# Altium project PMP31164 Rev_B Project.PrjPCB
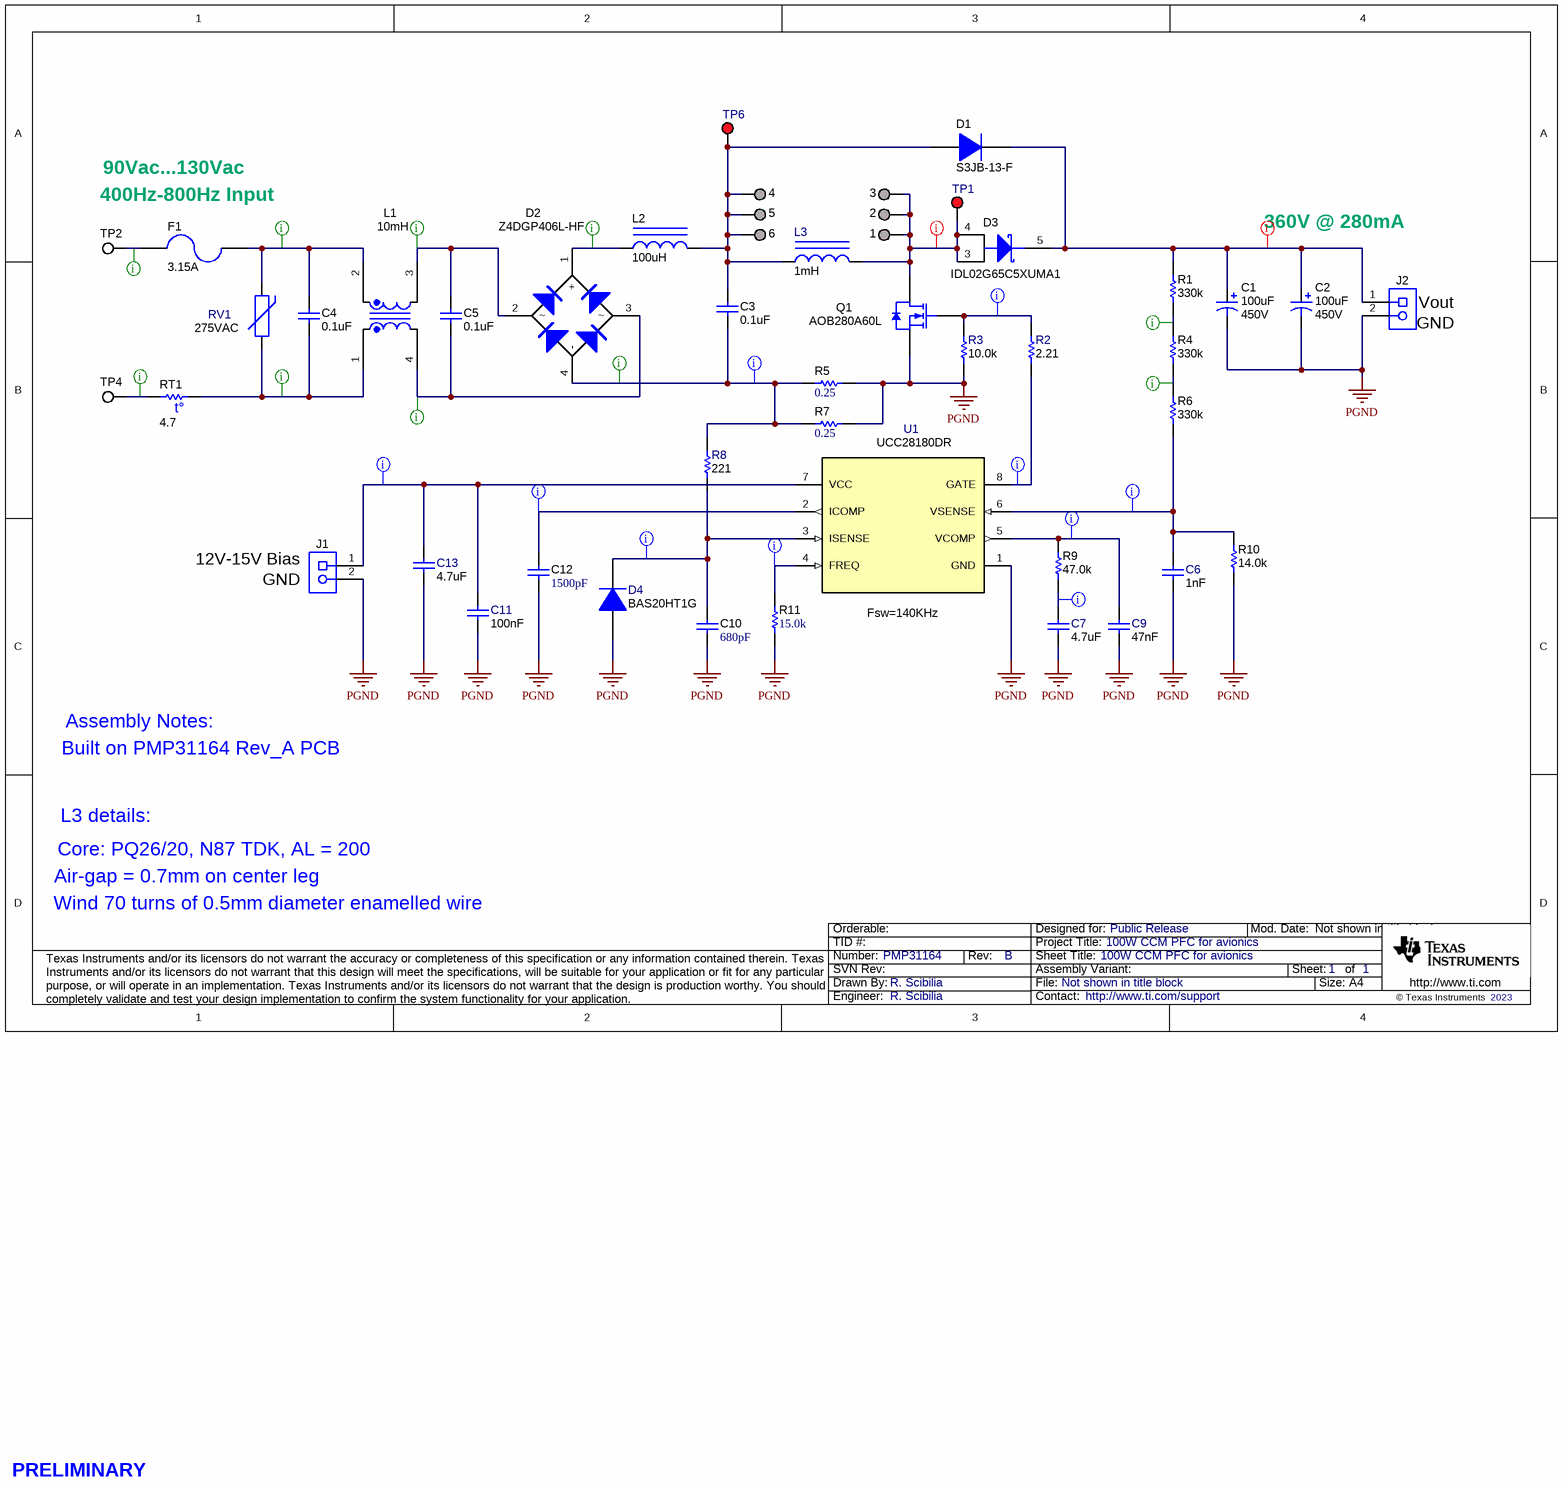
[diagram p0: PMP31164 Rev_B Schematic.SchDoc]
CopyrightYear: 2023; PCB_Layout: R. Scibilia; PCB_Rev: A; PRJ_Customer: Public Release; PRJ_Engineer: R. Scibilia; PRJ_Number: PMP31164; PRJ_Title: 100W CCM PFC for avionics; SCH_Rev: B; TechSupport: http://www.ti.com/support
1 sheet, 47 parts. Net scope: global (net labels, ports and power ports of the same name join across sheets).
Board file: PMP31164 Rev_A PCB.PcbDoc

## Sheet PMP31164 Rev_B Schematic.SchDoc: 100W CCM PFC for avionics
size A4; Date: Not shown in title block; ApprovedBy: Not shown in title block; CheckedBy: Not shown in title block; Author: Not shown in title block; CompanyName: Not shown in title block; DrawnBy: R. Scibilia; Engineer: Not shown in title block; Organization: Not shown in title block; Address1: Not shown in title block; Address2: Not shown in title block; Address3: Not shown in title block; Address4: Not shown in title block; DocumentNumber: 2; Revision: Use project parameter SCH_Rev; SheetNumber: 1; SheetTotal: 1; PageSetup: Record=PageOptions¦CenterHorizontal=True¦CenterVertical=True¦PrintScale=0.96¦XCorrection=1.00¦YCorrection=1.00¦PrintKind=0¦BorderSize=5000000¦LeftOffset=0¦BottomOffset=0¦Orientation=2¦PaperLength=4200¦PaperWidth=2970¦Scale=100¦PaperSource=7¦PrintQuality=600¦MediaType=1¦DitherType=10¦PaperKind=A3¦PrintScaleMode=1; PRJ_Engineer: R. Scibilia; PRJ_Number: PMP31164

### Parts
C1  VDC_V: 450V  ValueDisplayed: 100uF  [SMQ_2200X2500]  (hidden comment: ESMQ451VSN101MP25S)
C2  VDC_V: 450V  ValueDisplayed: 100uF  [SMQ_2200X2500]  (hidden comment: ESMQ451VSN101MP25S)
C3  ValueDisplayed: 0.1uF  [CAPRR1500W60L1750T550H1250]  (hidden comment: ECQ-U2A104ML)
C4  ValueDisplayed: 0.1uF  [CAPRR1500W60L1750T550H1250]  (hidden comment: ECQ-U2A104ML)
C5  ValueDisplayed: 0.1uF  [CAPRR1500W60L1750T550H1250]  (hidden comment: ECQ-U2A104ML)
C6  Cap_F: 1nF  [0603]  (hidden comment: C0603C102K5RACTU)
C7  ValueDisplayed: 4.7uF  [0805_HV]  (hidden comment: C2012X5R1E475K125AB)
C9  Cap_F: 47nF  [0603]  (hidden comment: 06033C473JAT2A)
C10  ValueDisplayed: 680pF  [0603]  (hidden comment: GRM1885C1H681JA01D)
C11  Cap_F: 100nF  [0603]  (hidden comment: C1608X7R1H104K080AA)
C12  ValueDisplayed: 1500pF  [0603]  (hidden comment: GRM1885C1H152JA01D)
C13  ValueDisplayed: 4.7uF  [0805_HV]  (hidden comment: C2012X5R1E475K125AB)
D1  S3JB-13-F  [SMB]
D2  Z4DGP406L-HF  [Z4-D]
D3  IDL02G65C5XUMA1  [PG-VSON-4]
D4  BAS20HT1G  [SOD-323]
F1  Irating_A: 3.15A  [FUSE_372]  (hidden comment: 37213150001)
J1  39357-0002  [MOLEX_39357-0002]  (value not drawn)
J2  39357-0002  [MOLEX_39357-0002]  (value not drawn)
L1  value 10mH  [WE-CMB_M]  (hidden comment: 744823210)
L2  ValueDisplayed: 100uH  [WE-PD_1210]  (hidden comment: 7447709101)
L3  value 1mH  [WE-PD_1210]  (hidden comment: TBD)
Q1  AOB280A60L  [DDPAK]
R1  ValueDisplayed: 330k  [1206]  (hidden comment: RC1206FR-07330KL)
R2  ValueDisplayed: 2.21  [0805_HV]  (hidden comment: CRCW08052R21FKEA)
R3  ValueDisplayed: 10.0k  [0603]  (hidden comment: CRCW060310K0FKEA)
R4  ValueDisplayed: 330k  [1206]  (hidden comment: RC1206FR-07330KL)
R5  ValueDisplayed: 0.25  [2010]  (hidden comment: CSRN2010FKR250)
R6  ValueDisplayed: 330k  [1206]  (hidden comment: RC1206FR-07330KL)
R7  ValueDisplayed: 0.25  [2010]  (hidden comment: CSRN2010FKR250)
R8  ValueDisplayed: 221  [0603]  (hidden comment: CRCW0603221RFKEA)
R9  ValueDisplayed: 47.0k  [0603]  (hidden comment: RC0603FR-0747KL)
R10  ValueDisplayed: 14.0k  [0603]  (hidden comment: CRCW060314K0FKEA)
R11  ValueDisplayed: 15.0k  [0603]  (hidden comment: RC0603FR-0715KL)
RT1  value 4.7  [S237]  (hidden comment: B57237S0479M000)
RV1  value 275VAC  [Epcos_B72220S0271K101]  (hidden comment: B72220S0271K101)
TP1  5000  [Keystone5000]  (value not drawn)
TP2  5012  [Keystone5012]  (value not drawn)
TP4  5012  [Keystone5012]  (value not drawn)
TP6  5000  [Keystone5000]  (value not drawn)
TP11  1  [TESTPOINT]  (no BOM)
TP12  2  [TESTPOINT]  (no BOM)
TP13  3  [TESTPOINT]  (no BOM)
TP14  4  [TESTPOINT]  (no BOM)
TP15  5  [TESTPOINT]  (no BOM)
TP16  6  [TESTPOINT]  (no BOM)
U1  UCC28180DR  [D0008A_N]

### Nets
PGND: C1.2(-) C2.2(-) C6.2 C7.2 C9.2 C10.2 C11.2 C12.2 C13.2 D4.2(A) J1.2 J2.2 Q1.3(S) R3.1 R5.2 R7.2 R10.1 R11.1 U1.1(GND)
NetC1_1: C1.1(+) C2.1(+) D1.1(K) D3.5(K) J2.1 R1.2
NetC3_1: C3.1 D1.2(A) L2.2 L3.1 TP6.1 TP14.1 TP15.1 TP16.1
NetC3_2: C3.2 D2.4(-) R5.1 R7.1 R8.2
NetC4_1: C4.1 F1.1 L1.2 RV1.2
NetC4_2: C4.2 L1.1 RT1.2 RV1.1
NetC5_1: C5.1 D2.2 L1.3
NetC5_2: C5.2 D2.3 L1.4
NetC6_1: C6.1 R6.1 R10.2 U1.6(VSENSE)
NetC7_1: C7.1 R9.1
NetC9_1: C9.1 R9.2 U1.5(VCOMP)
NetC10_1: C10.1 D4.1(K) R8.1 U1.3(ISENSE)
NetC11_1: C11.1 C13.1 J1.1 U1.7(VCC)
NetC12_1: C12.1 U1.2(ICOMP)
NetD2_1: D2.1(+) L2.1
NetD3_3: D3.3(A) D3.4(A) L3.2 Q1.2(D) TP1.1 TP11.1 TP12.1 TP13.1
NetF1_2: F1.2 TP2.1
NetQ1_1: Q1.1(G) R2.2 R3.2
NetR1_1: R1.1 R4.2
NetR2_1: R2.1 U1.8(GATE)
NetR4_1: R4.1 R6.2
NetR11_2: R11.2 U1.4(FREQ)
NetRT1_1: RT1.1 TP4.1

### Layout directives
rule Undefined; rule Clearance Constraint [Clearance = 30mil]: NetC1_1, NetC5_1, NetC5_2, NetD3_3
rule Undefined; rule Clearance Constraint [Clearance = 10mil]: NetC3_2, NetC6_1, NetC7_1, NetC9_1, NetC10_1, NetC11_1, NetC12_1, NetQ1_1, NetR2_1, NetR11_2
rule Undefined; rule Clearance Constraint [Clearance = 20mil]: NetC3_2, NetC4_1, NetC4_2, NetD2_1, NetF1_2, NetR1_1, NetR4_1, NetRT1_1

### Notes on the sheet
- 90Vac...130Vac
- 400Hz-800Hz Input
- 360V @ 280mA
- (near J2) Vout
- (near J2) GND
- (near J1) 12V-15V Bias
- (near J1) GND
- (near U1) Fsw=140KHz
- Assembly Notes:
- Built on PMP31164 Rev_A PCB
- L3 details:
- Core: PQ26/20, N87 TDK, AL = 200
- Air-gap = 0.7mm on center leg
- Wind 70 turns of 0.5mm diameter enamelled wire
- PRELIMINARY

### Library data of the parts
C1 C2 = CMP-0010054-2: CAP, AL, 100 uF, 450 V, +/- 20%, TH; Manufacturer: Chemi-Con; TaMin_C: -25°C; Polarized: Y; SizeAreaWB_mm2: 576; Value1: Unknown; U/M: EA; Value: 100uF; TaMax_C: 85°C; SizeZ_mm: 27; SizeX_mm: 22; Cap_Case: 22x25; SizeArea_mm2: 484; CompType: Capacitor; Cap_F: 100µF; IRMS_A: 930mA; AEC Category: Q200
C3-C5 = CMP-0012496-3: CAP, Film, 0.1 uF, 275 V, +/- 20%, TH; Manufacturer: Panasonic; TaMin_C: -40°C; Polarized: N; Value1: Unknown; Value: 0.1uF; TaMax_C: 100°C; Cap_Case: Radial 17.5x5.5x12.5; Value2: 275V; Cap_F: 100nF; AEC Category: Q200
C6 = CMP-0006847-4: CAP, CERM, 1000 pF, 50 V, +/- 10%, X7R, 0603; Manufacturer: Kemet; TaMin_C: -55°C; Polarized: N; SizeAreaWB_mm2: 4.68; Value1: Unknown; U/M: EA; Value: 1000pF; TaMax_C: 125°C; SizeZ_mm: 1; SizeX_mm: 1.6; SizeY_mm: 0.8; Value2: 50V; SizeArea_mm2: 1.28; AEC Category: Q200
C7 C13 = CMP-0007829-2: CAP, CERM, 4.7 uF, 25 V, +/- 10%, X5R, 0805; Manufacturer: TDK; TaMin_C: -55°C; Polarized: N; SizeAreaWB_mm2: 6.75; Value1: Unknown; U/M: EA; Value: 4.7uF; TaMax_C: 85°C; SizeZ_mm: 1.45; SizeX_mm: 2; SizeY_mm: 1.25; Cap_Case: 0805; Value2: 25V; SizeArea_mm2: 2.5; Cap_F: 4.7µF; AEC Category: Q200
C9 = CMP-0006757-5: CAP, CERM, 0.047 uF, 25 V, +/- 5%, X7R, 0603; Manufacturer: AVX; TaMin_C: -55°C; ESR_ohm: 52m; Polarized: N; SizeAreaWB_mm2: 4.68; Value1: 0.052 ohm; U/M: EA; TaMax_C: 125°C; SizeZ_mm: 1; SizeX_mm: 1.6; SizeY_mm: 0.8; Value2: 25V; SizeArea_mm2: 1.28; AEC Category: Q200
C10 = CMP-0007229-4: CAP, CERM, 680 pF, 50 V, +/- 5%, C0G/NP0, 0603; Manufacturer: MuRata; TaMin_C: -55°C; Polarized: N; SizeAreaWB_mm2: 4.68; Value1: Unknown; U/M: EA; Value: 680pF; TaMax_C: 125°C; SizeZ_mm: 1; SizeX_mm: 1.6; SizeY_mm: 0.8; Value2: 50V; SizeArea_mm2: 1.28; AEC Category: Q200
C11 = CMP-0007044-5: CAP, CERM, 0.1 uF, 50 V, +/- 10%, X7R, 0603; Manufacturer: TDK; TaMin_C: -55°C; ESR_ohm: 29.6m; Polarized: N; SizeAreaWB_mm2: 4.68; Value1: 0.0296 ohm; U/M: EA; Value: 0.1uF; TaMax_C: 125°C; SizeZ_mm: 1; SizeX_mm: 1.6; SizeY_mm: 0.8; Value2: 50V; SizeArea_mm2: 1.28; IRMS_A: 971.99mA; AEC Category: Q200
C12 = CMP-0007186-4: CAP, CERM, 1500 pF, 50 V, +/- 5%, C0G/NP0, 0603; Manufacturer: MuRata; TaMin_C: -55°C; Polarized: N; SizeAreaWB_mm2: 4.68; Value1: Unknown; U/M: EA; Value: 1500pF; TaMax_C: 125°C; SizeZ_mm: 1; SizeX_mm: 1.6; SizeY_mm: 0.8; Value2: 50V; SizeArea_mm2: 1.28; Cap_F: 1.5nF; AEC Category: Q200
D1 = CMP-0076890-2: Diode, Standard, 600 V, 3 A, SMB; Manufacturer: Diodes Inc.; Value1: 3A; TJmax_C: 150°C; RJC_CperW: 20.0; Green_REACh: Passed; Value2: 0.92V; Vf_V: 920mV; Green_Lifecycle: Active; SizeX_mm: 5.6; SizeAreaWB_mm2: 44.156; SizeZ_mm: 2.6; SizeArea_mm2: 21.336; Vr_V: 600V; SizeY_mm: 3.81; AEC Category: Q101
D2 = CMP-0029244-3: Diode, P-N-Bridge, 600 V, 4 A, Z4-D; Manufacturer: Comchip Technology; Value1: 4A; SizeZ_mm: 1.55; Value: 600V; SizeArea_mm2: 85.05; SizeY_mm: 8.1; SizeAreaWB_mm2: 126.25; Value2: 0.95V; Green_REACh: Incomplete; TJmax_C: 175°C; Green_Lifecycle: Not Set; Vf_V: 950mV; AEC Qualified: N; AEC Category: Q101; SizeX_mm: 10.5
D3 = CMP-0076996-2: Diode, Schottky, 650 V, 2 A, PG-VSON-4; Manufacturer: Infineon Technologies; Value2: 1.7V; Io_A: 2A; Value: 650V; Green_Lifecycle: Not Set; SizeZ_mm: 1.1; SizeAreaWB_mm2: 100.0; TJmax_C: 150°C; AEC Category: Q101; SizeArea_mm2: 64.0; SizeX_mm: 8.0; Green_REACh: Incomplete
D4 = CMP-0029150-2: Diode, Switching, 200 V, 0.2 A, AEC-Q101, SOD-323; Manufacturer: ON Semiconductor; Value2: 1.25V; Value1: 0.2A; SizeZ_mm: 1; Green_REACh: Incomplete; SizeArea_mm2: 3.645; Vr_V: 200V; SizeX_mm: 2.7; TJmax_C: 150°C; Io_A: 200mA; Value: 200V; Green_Lifecycle: Not Set; SizeAreaWB_mm2: 8.695; AEC Qualified: Y; AEC Category: Q101; SizeY_mm: 1.35
F1 = CMP-0003557-2: Fuse, 3.15 A, 250VAC/VDC, TH; Manufacturer: Littelfuse; VAC_V: 250V
J1 J2 = CMP-0055341-1: Terminal Block, 3.5 mm, 2x1, Tin, TH; Manufacturer: Molex; CNHeader: FALSE; Green_Lifecycle: Not Set; Green_REACh: Incomplete; CT: TRUE
L1 = CMP-0076828-1: Coupled inductor, 10 mH, 2 A, 0.125 ohm, TH; Manufacturer: Wurth Elektronik; SizeAreaWB_mm2: 513.0; SizeArea_mm2: 425.0; AEC Category: Q200; SizeZ_mm: 26.5; SizeY_mm: 17.0; DCR_ohm: 0.125; SizeX_mm: 25.0
L2 = CMP-0064536-2: Inductor, Shielded Drum Core, Ferrite, 100 uH, 2.5 A, 0.1 ohm, SMD; Manufacturer: Wurth Elektronik; Isat: 3.1A @ 10% inductance drop; Irms: 2.5A @ 40C rise; Green_Lifecycle: Active; SizeAreaWB_mm2: 196; DCR_ohm: 0.1; Green_REACh: Passed; Value1: 0.1 ohm; Value: 100uH; Imax_A: 2.5A; SizeZ_mm: 10; SizeX_mm: 12; SizeArea_mm2: 144; Ind_H: 100µH; AEC Category: Q200
L3 = CMP-0064759-2: Inductor, Ferrite, 1mH, 0.3 Ohm, te, 330 uH, 4 A(sat), TH; Isat: 4A @ 10% inductance drop; Irms: 2A @ 40C rise; Green_Lifecycle: Active; SizeAreaWB_mm2: 196; DCR_ohm: 0.3; Green_REACh: Passed; Value1: 0.3 ohm; Imax_A: 4A; SizeZ_mm: 10; SizeX_mm: 12; Value2: 2A; SizeArea_mm2: 144; AEC Category: Q200
Q1 = CMP-0081192-2: MOSFET, N-CH, 650 V, 56 A, DDPAK; Alternate Manufacturer: None; Manufacturer: Alpha & Omega; AEC Qualified: N; IdsMax_A: 56A; SizeArea_mm2: 154.8892; Value2: 23.5 nC; ChMode: Enhancement; QgTyp_nC: 20; VdsMax_V: 650V; SizeX_mm: 15.245; SizeZ_mm: 4.445; Vgs_V: 20V; SizeAreaWB_mm2: 209.6992; Value1: 0.28 ohm; AEC Category: Q101; SizeY_mm: 10.16
R1 R4 R6 = CMP-0018205-2: RES, 330 k, 1%, 0.25 W, 1206; Manufacturer: Yageo America; Power_W: 250mW; TempCo: 100 ppm/C; U/M: EA; Value: 330k; SizeX_mm: 3.2; SizeY_mm: 1.6; SizeZ_mm: 1.35; Value2: 0.25W; SizeArea_mm2: 5.12; VDC_V: 200V; AEC Category: Q200
R2 = CMP-0021145-3: RES, 2.21, 1%, 0.125 W, AEC-Q200 Grade 0, 0805; Manufacturer: Vishay-Dale; Power_W: 125mW; TempCo: 100 ppm/C; Value_Code: 2R21; Value: 2.21; EIA_Code: E96; SizeX_mm: 2; SizeY_mm: 1.25; SizeZ_mm: 1.45; Value2: 0.125W; SizeArea_mm2: 2.5; AEC Qualified: Y; VDC_V: 150V; AEC Category: Q200; AEC Grade: 0
R3 = CMP-0021998-4: RES, 10.0 k, 1%, 0.1 W, AEC-Q200 Grade 0, 0603; Manufacturer: Vishay-Dale; Power_W: 100mW; TempCo: 100 ppm/C; Value_Code: 10k0; Value: 10.0k; EIA_Code: E96; Res_ohm: 10k; SizeX_mm: 1.6; SizeY_mm: 0.8; SizeZ_mm: 1; Value2: 0.1W; SizeArea_mm2: 1.28; AEC Qualified: Y; VDC_V: 75V; AEC Category: Q200; AEC Grade: 0
R5 R7 = CMP-0016526-2: RES, 0.25, 1%, 1 W, 2010; Manufacturer: Stackpole Electronics Inc; Power_W: 1W; TempCo: 250 ppm/C; Value_Code: R250; U/M: EA; Value: 0.25; SizeX_mm: 5; SizeY_mm: 2.5; SizeZ_mm: 1.66; SizeArea_mm2: 12.5; AEC Category: Q200
R8 = CMP-0022217-5: RES, 221, 1%, 0.1 W, AEC-Q200 Grade 0, 0603; Manufacturer: Vishay-Dale; Power_W: 100mW; TempCo: 100 ppm/C; Value_Code: 221R; Value: 221; EIA_Code: E96; SizeX_mm: 1.6; SizeY_mm: 0.8; SizeZ_mm: 1; Value2: 0.1W; SizeArea_mm2: 1.28; AEC Qualified: Y; VDC_V: 75V; AEC Category: Q200; AEC Grade: 0
R9 = CMP-0023133-5: RES, 47.0 k, 1%, 0.1 W, 0603; Manufacturer: Yageo; Power_W: 100mW; TempCo: 100 ppm/C; Value_Code: 47k0; Value: 47.0k; Res_ohm: 47k; SizeX_mm: 1.6; SizeY_mm: 0.8; SizeZ_mm: 1; Value2: 0.1W; SizeArea_mm2: 1.28; AEC Qualified: N; VDC_V: 75V; AEC Category: Q200; SizeAreaWB_mm2: 4.68
R10 = CMP-0022054-4: RES, 14.0 k, 1%, 0.1 W, AEC-Q200 Grade 0, 0603; Manufacturer: Vishay-Dale; Power_W: 100mW; TempCo: 100 ppm/C; Value_Code: 14k0; Value: 14.0k; EIA_Code: E96; Res_ohm: 14k; SizeX_mm: 1.6; SizeY_mm: 0.8; SizeZ_mm: 1; Value2: 0.1W; SizeArea_mm2: 1.28; AEC Qualified: Y; VDC_V: 75V; AEC Category: Q200; AEC Grade: 0
R11 = CMP-0022816-5: RES, 15.0 k, 1%, 0.1 W, 0603; Manufacturer: Yageo; Power_W: 100mW; TempCo: 100 ppm/C; Value_Code: 15k0; Value: 15.0k; EIA_Code: E96; Res_ohm: 15k; SizeX_mm: 1.6; SizeY_mm: 0.8; SizeZ_mm: 1; Value2: 0.1W; SizeArea_mm2: 1.28; AEC Qualified: N; VDC_V: 75V; AEC Category: Q200; SizeAreaWB_mm2: 4.68
RT1 = CMP-0002554-2: Thermistor NTC, 4.70 ohm, 20%, 15x7mm; Manufacturer: TDK; TaMax_C: 170°C; SizeX_mm: 15; SizeY_mm: 7.5; TaMin_C: -55°C; Power_W: 3.1W; SizeZ_mm: 47; SizeArea_mm2: 112.5; SizeAreaWB_mm2: 161.5; U/M: EA
RV1 = CMP-0001856-2: Varistor 275 VAC, 100 A, TH; Manufacturer: TDK
TP1 TP6 = CMP-0055137-2: Test Point, Miniature, Red, TH; Manufacturer: Keystone Electronics; Green_REACh: Passed; Green_Lifecycle: Active; ContactFinish: Silver; CNHeader: FALSE; CT: TRUE
TP2 TP4 = CMP-0055149-2: Test Point, Multipurpose, White, TH; Manufacturer: Keystone Electronics; ContactFinish: Silver; CT: TRUE; CNHeader: FALSE; Green_Lifecycle: Active; Green_REACh: Passed
TP11-TP16 = CMP-0078143-3: TEST POINT.  No entry in BOM.
U1 = CMP-0074100-1: 8-PIN CONTINUOUS CONDUCTION MODE (CCM) PFC CONTROLLER, D0008A (SOIC-8); Alternate Manufacturer: Texas Instruments; SizeAreaWB_mm2: 56.58; U/M: EA; SizeZ_mm: 1.75; SizeX_mm: 4.9; SizeY_mm: 6.2; SizeArea_mm2: 30.38; CompType: IC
